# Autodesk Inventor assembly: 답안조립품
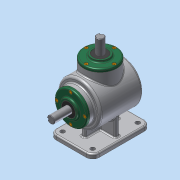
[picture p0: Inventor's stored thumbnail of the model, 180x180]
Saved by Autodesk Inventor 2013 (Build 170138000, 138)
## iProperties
Created: 2016-09
Part Number: 답안조립품
Document SubType Name: Assembly
Designer: Administrator
Author: Administrator
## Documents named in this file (14)
- C:\Users\Administrator\Desktop\460908V1017\답안조립품.iam
- C:\Users\Administrator\Desktop\460908V1017\1.본체.ipt
- C:\Users\Administrator\Desktop\460908V1017\커버.ipt
- C:\Users\Administrator\Desktop\460908V1017\베어링 6203.ipt
- C:\Users\Administrator\Desktop\460908V1017\오일실 17 32 8.ipt
- C:\Users\Administrator\Desktop\460908V1017\메인 축.ipt
- 메인 축.ipt
- C:\Users\Administrator\Desktop\460908V1017\서브 축.ipt
- 서브 축.ipt
- C:\Users\Administrator\Desktop\460908V1017\키 5x5.ipt
- C:\Users\Administrator\Desktop\460908V1017\키 4x4.ipt
- C:\Users\Administrator\Desktop\460908V1017\메인 베벨기어.ipt
- C:\Users\Administrator\Desktop\460908V1017\서브 베벨기어.ipt
- C:\Users\Administrator\Desktop\460908V1017\M4.ipt
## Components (9 placed, 2 different names)
1. 1.본체:1
2. M4:1
3. M4:3
4. M4:4
5. M4:5
6. M4:2
7. M4:6
8. M4:7
9. M4:8
